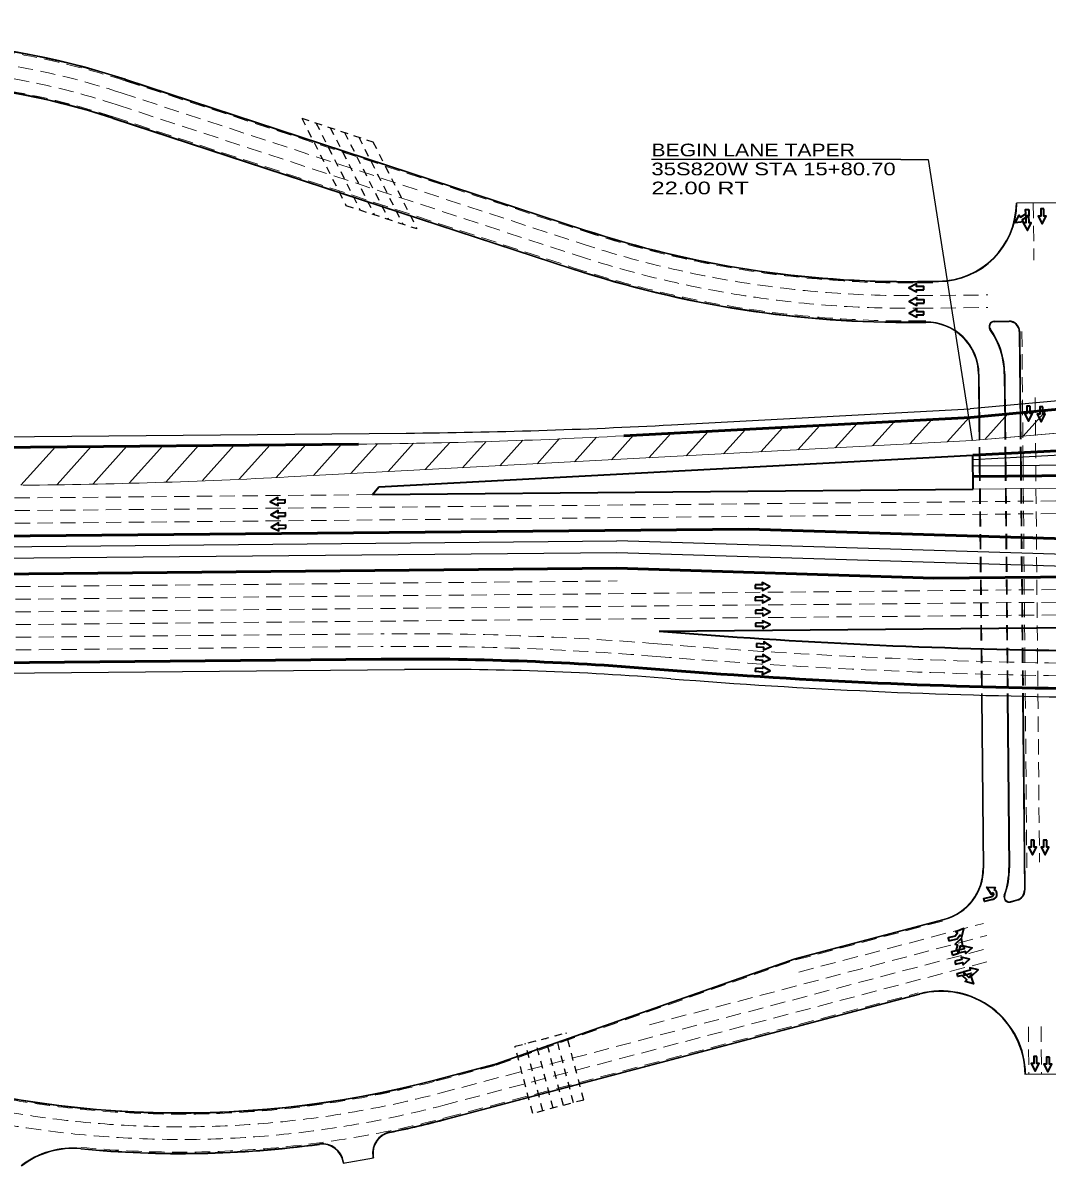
# Model space of a CAD drawing. Extents: x 2326434 to 2368642, y 6985225 to 6995090.
# Drawn here: x 2329823 to 2330793, y 6990688 to 6991772 of the extents above; entities that cross this region are included whole.
import ezdxf

# ---------------------------------------------------------------- set-up
doc = ezdxf.new("R2010")
doc.units = 0
doc.header["$LTSCALE"] = 4.8
doc.linetypes.add('MEDIUM_DASHED', pattern=[4.5, 3, -1.5])
doc.linetypes.add('SHORT_DASHED', pattern=[2.7, 1.5, -1.2])
for name, color, linetype, lineweight in [('10', 7, 'Continuous', 35), ('26', 7, 'Continuous', 25), ('27', 7, 'Continuous', 25), ('28', 7, 'Continuous', 25), ('33', 7, 'SHORT_DASHED', 25), ('40', 7, 'Continuous', 35), ('5', 7, 'Continuous', 25), ('50', 7, 'MEDIUM_DASHED', 13)]:
    doc.layers.add(name, color=color, linetype=linetype, lineweight=lineweight)

msp = doc.modelspace()

# ---------------------------------------------------------------- linework, layer by layer
at = {"layer": '10'}
for p, q in [((2330160.246, 6991332.035), (2330723.1, 6991362.027)), ((2330723.399, 6991330.029), (2330723.1, 6991362.028)), ((2330154.405, 6991324.713), (2330160.246, 6991332.035)), ((2330154.405, 6991324.713), (2330723.399, 6991330.029)), ((2330426.072, 6991195.246), (2330819.65, 6991198.923))]:
    msp.add_line(p, q, dxfattribs=at)
for centre, radius, start, end in [((2331921.237, 6992748.984), 1265.239, 273.05017, 273.05017), ((2330888.37, 6996870.024), 5693.578, 265.34266, 269.30964)]:
    msp.add_arc(centre, radius, start, end, dxfattribs=at)
at = {"layer": '26'}
for p, q in [((2329663.567, 6991378.13), (2330186.355, 6991383.014)), ((2330723.193, 6991352.028), (2332252.211, 6991366.314)), ((2329664.538, 6991274.135), (2330385.724, 6991280.873)), ((2329665.659, 6991154.14), (2330184.765, 6991158.99))]:
    msp.add_line(p, q, dxfattribs=at)
at = {"layer": '26', "lineweight": 53}
for p, q in [((2329663.66, 6991368.13), (2330141.09, 6991372.591)), ((2330723.287, 6991342.029), (2332252.305, 6991356.314)), ((2329664.445, 6991284.134), (2330510.625, 6991292.04)), ((2330686.071, 6991245.677), (2332092.005, 6991258.812)), ((2329665.566, 6991164.139), (2330162.725, 6991168.784))]:
    msp.add_line(p, q, dxfattribs=at)
at = {"layer": '27', "lineweight": 53}
for p, q in [((2330723.1, 6991362.027), (2332517.509, 6991457.643)), ((2330720.933, 6991397.962), (2331019.869, 6991425.908)), ((2330392.434, 6991380.458), (2330720.933, 6991397.962))]:
    msp.add_line(p, q, dxfattribs=at)
at = {"layer": '27'}
for p, q in [((2330723.061, 6991358.019), (2332517.722, 6991453.649)), ((2331019.444, 6991433.897), (2330720.507, 6991405.951)), ((2330437.699, 6991390.881), (2330720.507, 6991405.951))]:
    msp.add_line(p, q, dxfattribs=at)
for centre, radius, start, end in [((2330132.827, 6997112.342), 5729.578, 270.53529, 273.05017), ((2330211.529, 6988294.326), 2864.789, 85.48726, 90.53529), ((2330888.37, 6996870.024), 5737.578, 265.48726, 269.30964)]:
    msp.add_arc(centre, radius, start, end, dxfattribs=at)
at = {"layer": '27', "lineweight": 53}
for centre, radius, start, end in [((2330189.489, 6988304.12), 2864.789, 85.33564, 90.53529), ((2330888.37, 6996870.024), 5729.578, 265.33564, 269.30964)]:
    msp.add_arc(centre, radius, start, end, dxfattribs=at)
at = {"layer": '28'}
for p, q in [((2329920.311, 6991717.972), (2330355.197, 6991575.35)), ((2329920.467, 6991718.448), (2330355.352, 6991575.825)), ((2329908.313, 6991681.39), (2330343.199, 6991538.767)), ((2329908.469, 6991681.865), (2330343.355, 6991539.242)), ((2330854.998, 6991601.813), (2330764.308, 6991600.966)), ((2330670.791, 6991526.932), (2330690.507, 6991527.116)), ((2330670.795, 6991526.432), (2330690.511, 6991526.616)), ((2330671.15, 6991488.434), (2330678.437, 6991488.502)), ((2330671.155, 6991487.934), (2330678.441, 6991488.002)), ((2330743.365, 6991489.109), (2330757.433, 6991489.24)), ((2330743.369, 6991488.609), (2330757.438, 6991488.74)), ((2330767.026, 6991479.329), (2330767.846, 6991391.636)), ((2330767.526, 6991479.334), (2330768.346, 6991391.658)), ((2330728.402, 6991438.967), (2330728.848, 6991391.288)), ((2330728.902, 6991438.971), (2330729.348, 6991391.293)), ((2330752.901, 6991439.195), (2330753.346, 6991391.517)), ((2330753.401, 6991439.2), (2330753.846, 6991391.522)), ((2330768.138, 6991360.421), (2330768.212, 6991352.449)), ((2330768.637, 6991360.447), (2330768.712, 6991352.454)), ((2330729.155, 6991358.344), (2330729.214, 6991352.085)), ((2330729.655, 6991358.37), (2330729.714, 6991352.089)), ((2330753.644, 6991359.649), (2330753.713, 6991352.314)), ((2330754.144, 6991359.675), (2330754.213, 6991352.318)), ((2330810.865, 6991267.844), (2330385.724, 6991280.873)), ((2329754.855, 6991263.978), (2330385.827, 6991269.873)), ((2330385.827, 6991269.873), (2330810.967, 6991256.844)), ((2330731.258, 6991133.337), (2330732.778, 6990970.753)), ((2330731.758, 6991133.341), (2330733.278, 6990970.758)), ((2330755.757, 6991133.565), (2330757.277, 6990970.982)), ((2330756.257, 6991133.57), (2330757.777, 6990970.987)), ((2330770.256, 6991133.716), (2330771.974, 6990949.936)), ((2330770.757, 6991133.706), (2330772.474, 6990949.941)), ((2330758.703, 6990939.024), (2330764.902, 6990940.662)), ((2330758.831, 6990938.541), (2330765.03, 6990940.179)), ((2330554.86, 6990885.152), (2330695.928, 6990922.434)), ((2330554.987, 6990884.668), (2330696.056, 6990921.95)), ((2330270.934, 6990785.291), (2330554.86, 6990885.152)), ((2330271.081, 6990784.813), (2330554.987, 6990884.668)), ((2330224.442, 6990733.182), (2330672.671, 6990851.642)), ((2330224.569, 6990732.699), (2330672.799, 6990851.158)), ((2330214.604, 6990770.404), (2330270.934, 6990785.291)), ((2330214.732, 6990769.921), (2330271.081, 6990784.813)), ((2330126.563, 6990692.016), (2330126.715, 6990691.036)), ((2330126.715, 6990691.036), (2330155.332, 6990696.033)), ((2330127.057, 6990692.092), (2330127.209, 6990691.113)), ((2330154.619, 6990697.37), (2330154.838, 6990695.956)), ((2330155.113, 6990697.447), (2330155.332, 6990696.033))]:
    msp.add_line(p, q, dxfattribs=at)
at = {"layer": '28', "linetype": 'MEDIUM_DASHED'}
for p, q in [((2330728.848, 6991391.288), (2330729.155, 6991358.344)), ((2330729.348, 6991391.293), (2330729.655, 6991358.37)), ((2330753.346, 6991391.517), (2330753.644, 6991359.649)), ((2330753.846, 6991391.522), (2330754.144, 6991359.675)), ((2330767.846, 6991391.636), (2330768.138, 6991360.421)), ((2330768.346, 6991391.658), (2330768.637, 6991360.447)), ((2330729.214, 6991352.085), (2330731.258, 6991133.337)), ((2330729.714, 6991352.089), (2330731.758, 6991133.341)), ((2330753.713, 6991352.314), (2330755.757, 6991133.565)), ((2330754.213, 6991352.318), (2330756.257, 6991133.57)), ((2330768.212, 6991352.449), (2330770.256, 6991133.716)), ((2330768.712, 6991352.454), (2330770.757, 6991133.706))]:
    msp.add_line(p, q, dxfattribs=at)
at = {"layer": '28', "lineweight": 53}
for p, q in [((2330810.724, 6991282.843), (2330510.625, 6991292.04)), ((2329664.781, 6991248.136), (2330385.967, 6991254.874)), ((2330385.967, 6991254.874), (2330686.071, 6991245.677))]:
    msp.add_line(p, q, dxfattribs=at)
at = {"layer": '28'}
msp.add_lwpolyline([(2330773.606, 6990775.304), (2330805.132, 6990775.611), (2330806.565, 6990715.622)], dxfattribs=at)
for centre, radius, start, end in [((2329689.814, 6991015.138), 740.165, 71.84292, 104.46691), ((2329689.814, 6991015.138), 739.665, 71.84292, 104.46691), ((2329689.814, 6991015.138), 701.665, 71.84292, 104.46691), ((2329689.814, 6991015.138), 701.165, 71.84292, 104.46691), ((2330689.81, 6991601.613), 74.5, 270.53549, 359.50218), ((2330689.81, 6991601.613), 75, 270.53549, 359.50907), ((2330661.606, 6992509.657), 983.268, 251.84292, 270.53549), ((2330661.606, 6992509.657), 982.768, 251.84292, 270.53549), ((2330661.606, 6992509.657), 1021.768, 251.84292, 270.53549), ((2330661.606, 6992509.657), 1021.268, 251.84292, 270.53549), ((2330678.904, 6991438.504), 50, 0.53547, 90.53549), ((2330678.904, 6991438.504), 49.5, 0.53547, 90.53549), ((2330743.411, 6991484.109), 5, 90.53549, 215.25924), ((2330743.411, 6991484.109), 4.5, 90.53549, 215.25924), ((2330678.904, 6991438.504), 74, 0.53547, 35.25924), ((2330678.904, 6991438.504), 74.5, 0.53547, 35.25924), ((2330757.527, 6991479.24), 10, 0.53547, 90.53549), ((2330757.527, 6991479.24), 9.5, 0.53547, 90.53549), ((2330683.28, 6990970.291), 49.5, 284.80383, 0.53547), ((2330683.28, 6990970.291), 50, 284.80383, 0.53547), ((2330683.28, 6990970.291), 74, 340.08008, 0.53546), ((2330683.28, 6990970.291), 74.5, 340.08008, 0.53546), ((2330762.475, 6990949.847), 9.5, 284.80383, 0.53547), ((2330762.475, 6990949.847), 10, 284.80383, 0.53547), ((2330757.553, 6990943.375), 5, 160.08008, 284.80383), ((2330757.553, 6990943.375), 4.5, 160.08008, 284.80383), ((2330693.112, 6990774.297), 80, 0.53547, 104.80383), ((2330693.112, 6990774.297), 79.5, 0.53547, 104.80383), ((2329972.578, 6991686.191), 947.228, 249.88799, 284.80383), ((2329972.578, 6991686.191), 947.728, 249.88799, 284.80383), ((2329972.578, 6991686.191), 985.728, 281.59821, 284.80383), ((2329972.578, 6991686.191), 986.228, 281.59821, 284.80383), ((2330174.877, 6990700.508), 20.5, 101.59821, 188.80445), ((2330174.877, 6990700.508), 20, 101.59821, 188.80445), ((2329870.528, 6990625.36), 80, 84.50515, 127.7674), ((2329870.528, 6990625.36), 79.5, 84.50515, 127.7674), ((2329972.578, 6991686.191), 986.228, 264.50515, 277.66555), ((2329972.578, 6991686.191), 985.728, 264.50515, 277.66555), ((2330106.799, 6990688.954), 20.5, 8.80445, 97.66555), ((2330106.799, 6990688.954), 20, 8.80445, 97.66555)]:
    msp.add_arc(centre, radius, start, end, dxfattribs=at)
at = {"layer": '33'}
for p, q in [((2330087.287, 6991681.647), (2330154.774, 6991659.15)), ((2330100.785, 6991677.148), (2330142.717, 6991594.518)), ((2330114.282, 6991672.648), (2330156.17, 6991590.106)), ((2330127.779, 6991668.149), (2330169.623, 6991585.694)), ((2330141.277, 6991663.649), (2330183.076, 6991581.282)), ((2330154.774, 6991659.15), (2330196.528, 6991576.871)), ((2330335.166, 6990745.771), (2330318.424, 6990809.425)), ((2330344.837, 6990748.314), (2330328.095, 6990811.969)), ((2330354.508, 6990750.858), (2330337.766, 6990814.513)), ((2330315.823, 6990740.684), (2330299.081, 6990804.338)), ((2330325.494, 6990743.227), (2330308.752, 6990806.882)), ((2330354.508, 6990750.858), (2330306.152, 6990738.14))]:
    msp.add_line(p, q, dxfattribs=at)
for points in [[(2330087.287, 6991681.647), (2330129.264, 6991598.93), (2330196.528, 6991576.871)], [(2330306.152, 6990738.14), (2330289.41, 6990801.794), (2330337.766, 6990814.513)]]:
    msp.add_lwpolyline(points, dxfattribs=at)
at = {"layer": '40'}
for points in [[(2330776.129, 6991595.153), (2330776.157, 6991589.169), (2330769.801, 6991585.306), (2330771.188, 6991583.302), (2330763.117, 6991582.313), (2330766.889, 6991589.517), (2330768.094, 6991587.774), (2330773.181, 6991590.923), (2330773.101, 6991595.102)], [(2330776.157, 6991589.169), (2330773.157, 6991589.099), (2330773.315, 6991582.295), (2330770.879, 6991582.238), (2330774.824, 6991575.128), (2330778.434, 6991582.414), (2330776.315, 6991582.364)], [(2330790.375, 6991595.548), (2330787.374, 6991595.548), (2330787.374, 6991588.742), (2330784.937, 6991588.742), (2330788.716, 6991581.542), (2330792.494, 6991588.742), (2330790.375, 6991588.742)], [(2330676.611, 6991518.99), (2330676.609, 6991521.991), (2330669.802, 6991521.986), (2330669.801, 6991524.423), (2330662.603, 6991520.64), (2330669.806, 6991516.866), (2330669.804, 6991518.985)], [(2330676.839, 6991506.284), (2330676.837, 6991509.285), (2330670.03, 6991509.281), (2330670.029, 6991511.718), (2330662.831, 6991507.934), (2330670.034, 6991504.16), (2330670.032, 6991506.28)], [(2330676.759, 6991495.035), (2330676.757, 6991498.036), (2330669.95, 6991498.031), (2330669.948, 6991500.468), (2330662.751, 6991496.685), (2330669.953, 6991492.911), (2330669.952, 6991495.03)], [(2330777.351, 6991408.498), (2330774.351, 6991408.498), (2330774.351, 6991401.691), (2330771.913, 6991401.691), (2330775.692, 6991394.491), (2330779.471, 6991401.691), (2330777.351, 6991401.691)], [(2330789.491, 6991407.838), (2330786.49, 6991407.838), (2330786.49, 6991401.031), (2330784.053, 6991401.031), (2330787.832, 6991393.831), (2330791.61, 6991401.031), (2330789.491, 6991401.031)], [(2330071.621, 6991316.81), (2330071.514, 6991319.809), (2330064.712, 6991319.567), (2330064.625, 6991322.003), (2330057.564, 6991317.971), (2330064.894, 6991314.45), (2330064.818, 6991316.568)], [(2330071.993, 6991304.43), (2330071.887, 6991307.429), (2330065.084, 6991307.188), (2330064.998, 6991309.623), (2330057.936, 6991305.591), (2330065.266, 6991302.07), (2330065.191, 6991304.189)], [(2330072.29, 6991292.847), (2330072.183, 6991295.846), (2330065.381, 6991295.605), (2330065.294, 6991298.04), (2330058.233, 6991294.008), (2330065.562, 6991290.488), (2330065.487, 6991292.606)], [(2330516.877, 6991239.098), (2330516.93, 6991236.098), (2330523.735, 6991236.216), (2330523.778, 6991233.779), (2330530.911, 6991237.683), (2330523.646, 6991241.336), (2330523.683, 6991239.217)], [(2330516.877, 6991239.098), (2330516.93, 6991236.098), (2330523.735, 6991236.216), (2330523.778, 6991233.779), (2330530.911, 6991237.683), (2330523.646, 6991241.336), (2330523.683, 6991239.217)], [(2330516.964, 6991227.512), (2330517.017, 6991224.511), (2330523.822, 6991224.63), (2330523.865, 6991222.193), (2330530.998, 6991226.097), (2330523.733, 6991229.749), (2330523.77, 6991227.63)], [(2330516.964, 6991227.512), (2330517.017, 6991224.511), (2330523.822, 6991224.63), (2330523.865, 6991222.193), (2330530.998, 6991226.097), (2330523.733, 6991229.749), (2330523.77, 6991227.63)], [(2330517.113, 6991215.127), (2330517.165, 6991212.127), (2330523.971, 6991212.246), (2330524.013, 6991209.809), (2330531.147, 6991213.713), (2330523.882, 6991217.365), (2330523.919, 6991215.246)], [(2330517.113, 6991215.127), (2330517.165, 6991212.127), (2330523.971, 6991212.246), (2330524.013, 6991209.809), (2330531.147, 6991213.713), (2330523.882, 6991217.365), (2330523.919, 6991215.246)], [(2330517.214, 6991203.014), (2330517.267, 6991200.014), (2330524.072, 6991200.132), (2330524.115, 6991197.695), (2330531.248, 6991201.599), (2330523.983, 6991205.252), (2330524.02, 6991203.133)], [(2330517.214, 6991203.014), (2330517.267, 6991200.014), (2330524.072, 6991200.132), (2330524.115, 6991197.695), (2330531.248, 6991201.599), (2330523.983, 6991205.252), (2330524.02, 6991203.133)], [(2330518.251, 6991183.466), (2330518.061, 6991180.471), (2330524.854, 6991180.039), (2330524.699, 6991177.607), (2330532.125, 6991180.921), (2330525.179, 6991185.149), (2330525.044, 6991183.034)], [(2330517.373, 6991171.384), (2330517.183, 6991168.389), (2330523.976, 6991167.957), (2330523.821, 6991165.525), (2330531.247, 6991168.839), (2330524.301, 6991173.067), (2330524.166, 6991170.952)], [(2330517.185, 6991160.235), (2330516.994, 6991157.241), (2330523.787, 6991156.809), (2330523.632, 6991154.376), (2330531.058, 6991157.69), (2330524.112, 6991161.919), (2330523.978, 6991159.803)], [(2330781.299, 6990997.228), (2330778.298, 6990997.228), (2330778.298, 6990990.422), (2330775.861, 6990990.422), (2330779.639, 6990983.221), (2330783.418, 6990990.422), (2330781.299, 6990990.422)], [(2330793.116, 6990997.343), (2330790.115, 6990997.343), (2330790.115, 6990990.537), (2330787.678, 6990990.537), (2330791.457, 6990983.337), (2330795.235, 6990990.537), (2330793.116, 6990990.537)], [(2330700.484, 6990901.769), (2330708.2, 6990903.661), (2330710.894, 6990907.121), (2330712.756, 6990905.548), (2330714.516, 6990913.487), (2330706.983, 6990910.425), (2330708.602, 6990909.057), (2330706.477, 6990906.328), (2330699.77, 6990904.683)], [(2330703.669, 6990888.281), (2330709.42, 6990889.934), (2330711.346, 6990897.117), (2330713.659, 6990896.349), (2330712.344, 6990904.373), (2330706.487, 6990898.732), (2330708.498, 6990898.064), (2330706.902, 6990892.298), (2330702.869, 6990891.202)], [(2330709.42, 6990889.934), (2330708.646, 6990892.833), (2330715.222, 6990894.589), (2330714.593, 6990896.944), (2330722.525, 6990895.151), (2330716.544, 6990889.642), (2330715.997, 6990891.69)], [(2330705.93, 6990882.542), (2330706.667, 6990879.634), (2330713.265, 6990881.304), (2330713.864, 6990878.942), (2330719.916, 6990884.372), (2330712.008, 6990886.268), (2330712.529, 6990884.213)], [(2330708.27, 6990870.871), (2330714.087, 6990872.276), (2330719.31, 6990866.982), (2330720.941, 6990868.793), (2330723.762, 6990861.166), (2330715.884, 6990863.177), (2330717.302, 6990864.752), (2330713.066, 6990868.976), (2330709.018, 6990867.936)], [(2330714.087, 6990872.276), (2330714.846, 6990869.373), (2330721.431, 6990871.095), (2330722.048, 6990868.737), (2330728.058, 6990874.214), (2330720.136, 6990876.049), (2330720.672, 6990873.998)], [(2330783.722, 6990792.226), (2330780.721, 6990792.226), (2330780.721, 6990785.419), (2330778.284, 6990785.419), (2330782.062, 6990778.219), (2330785.841, 6990785.419), (2330783.722, 6990785.419)], [(2330795.861, 6990791.566), (2330792.861, 6990791.566), (2330792.861, 6990784.759), (2330790.423, 6990784.759), (2330794.202, 6990777.559), (2330797.981, 6990784.759), (2330795.861, 6990784.759)]]:
    msp.add_lwpolyline(points, close=True, dxfattribs=at)
for points in [[(2330741.781, 6990947.659), (2330740.785, 6990945.798), (2330736.219, 6990952.527), (2330744.351, 6990952.462), (2330743.201, 6990950.313)], [(2330741.836, 6990940.934), (2330734.107, 6990939.096), (2330733.413, 6990942.016), (2330741.351, 6990943.903), (2330741.302, 6990943.894)]]:
    msp.add_lwpolyline(points, dxfattribs=at)
for radius, end in [(4.997, 63.22063), (1.989, 65.29445)]:
    msp.add_arc((2330740.95, 6990945.852), radius, 280.21581, end, dxfattribs=at)
at = {"layer": '5'}
msp.add_line((2330654.791, 6991642.434), (2330418.636, 6991642.434), dxfattribs=at)
msp.add_lwpolyline([(2330654.791, 6991642.434), (2330680.763, 6991642.434), (2330722.355, 6991376.007)], dxfattribs=at)
at = {"layer": '50'}
for p, q in [((2329919.999, 6991717.022), (2330354.885, 6991574.4)), ((2329916.26, 6991705.62), (2330351.145, 6991562.997)), ((2329912.52, 6991694.217), (2330347.406, 6991551.595)), ((2329908.781, 6991682.815), (2330343.667, 6991540.193)), ((2330780.388, 6991601.116), (2330780.893, 6991547.08)), ((2330670.805, 6991525.432), (2330692.09, 6991525.631)), ((2330670.917, 6991513.433), (2330737.201, 6991514.052)), ((2330671.029, 6991501.433), (2330737.313, 6991502.053)), ((2330671.141, 6991489.434), (2330678.427, 6991489.502)), ((2330769.526, 6991479.353), (2330770.637, 6991360.554)), ((2330782.111, 6991416.806), (2330786.229, 6990976.223)), ((2329664.221, 6991308.133), (2332252.529, 6991332.315)), ((2329664.109, 6991320.133), (2330154.405, 6991324.713)), ((2329664.333, 6991296.134), (2332252.641, 6991320.316)), ((2329664.893, 6991236.136), (2330386.079, 6991242.874)), ((2329665.118, 6991212.137), (2332253.426, 6991236.319)), ((2329665.23, 6991200.138), (2332253.538, 6991224.32)), ((2329665.342, 6991188.138), (2330162.501, 6991192.783)), ((2329665.454, 6991176.139), (2330162.613, 6991180.784)), ((2330555.227, 6990883.698), (2330696.311, 6990920.984)), ((2330558.309, 6990872.1), (2330733.337, 6990918.357)), ((2330416.86, 6990822.305), (2330736.403, 6990906.755)), ((2330218.054, 6990757.352), (2330739.469, 6990895.154)), ((2330221.12, 6990745.751), (2330742.536, 6990883.552)), ((2330271.375, 6990783.856), (2330555.342, 6990883.733)), ((2330224.186, 6990734.149), (2330671.418, 6990852.345)), ((2330775.685, 6990820.376), (2330776.106, 6990775.328)), ((2330787.684, 6990820.489), (2330788.105, 6990775.445)), ((2330214.988, 6990768.954), (2330271.375, 6990783.856))]:
    msp.add_line(p, q, dxfattribs=at)
at = {"layer": '50', "linetype": 'Continuous'}
for p, q in [((2330770.799, 6991380.203), (2330792.799, 6991404.681)), ((2330628.053, 6991370.982), (2330648.851, 6991394.121)), ((2330663.358, 6991372.863), (2330684.156, 6991396.003)), ((2330698.663, 6991374.744), (2330719.462, 6991397.884)), ((2331022.739, 6991402.027), (2330722.355, 6991376.007)), ((2330734.346, 6991377.046), (2330756.102, 6991401.25)), ((2330416.221, 6991359.694), (2330437.02, 6991382.834)), ((2330451.527, 6991361.575), (2330472.325, 6991384.715)), ((2330486.832, 6991363.457), (2330507.63, 6991386.596)), ((2330522.137, 6991365.338), (2330542.935, 6991388.477)), ((2330557.442, 6991367.219), (2330578.241, 6991390.359)), ((2330592.748, 6991369.101), (2330613.546, 6991392.24)), ((2330141.09, 6991372.591), (2329663.66, 6991368.13)), ((2329923.876, 6991335.501), (2329955.656, 6991370.859)), ((2329958.549, 6991336.679), (2329989.555, 6991371.175)), ((2329993.332, 6991337.979), (2330023.454, 6991371.492)), ((2330028.115, 6991339.28), (2330057.353, 6991371.809)), ((2330063.204, 6991340.92), (2330091.252, 6991372.125)), ((2330074.514, 6991341.486), (2330722.355, 6991376.007)), ((2330098.474, 6991342.763), (2330125.151, 6991372.442)), ((2330133.779, 6991344.644), (2330159.103, 6991372.818)), ((2330169.085, 6991346.525), (2330193.272, 6991373.435)), ((2330204.39, 6991348.407), (2330227.666, 6991374.303)), ((2330239.695, 6991350.288), (2330262.06, 6991375.17)), ((2330275, 6991352.169), (2330296.645, 6991376.251)), ((2330310.306, 6991354.05), (2330331.641, 6991377.788)), ((2330345.611, 6991355.932), (2330366.637, 6991379.325)), ((2330380.916, 6991357.813), (2330401.714, 6991380.952)), ((2329821.326, 6991333.602), (2329853.959, 6991369.908)), ((2329855.498, 6991334.223), (2329887.858, 6991370.225)), ((2329889.687, 6991334.862), (2329921.757, 6991370.542)), ((2330723.399, 6991330.029), (2331404.275, 6991336.391))]:
    msp.add_line(p, q, dxfattribs=at)
for points in [[(2331988.987, 6991477.549), (2331019.869, 6991425.908), (2330720.933, 6991397.962), (2330392.434, 6991380.458)], [(2330074.514, 6991341.486), (2330722.355, 6991376.007), (2331022.739, 6991402.027), (2331911.828, 6991449.403)]]:
    msp.add_lwpolyline(points, dxfattribs=at)
at = {"layer": '50'}
for points in [[(2330770.637, 6991360.554), (2330770.712, 6991352.472), (2330774.304, 6990968.169)], [(2329665.005, 6991224.137), (2332090.455, 6991246.797), (2332253.314, 6991248.319)]]:
    msp.add_lwpolyline(points, dxfattribs=at)
for centre, radius, start, end in [((2329689.814, 6991015.138), 738.665, 71.84292, 104.46691), ((2329689.814, 6991015.138), 726.665, 71.84292, 104.46691), ((2329689.814, 6991015.138), 714.665, 71.84292, 104.46691), ((2329689.814, 6991015.138), 702.665, 71.84292, 104.46691), ((2330661.606, 6992509.657), 984.268, 251.84292, 270.53549), ((2330661.606, 6992509.657), 996.268, 251.84292, 270.53549), ((2330661.606, 6992509.657), 1008.268, 251.84292, 270.53549), ((2330661.606, 6992509.657), 1020.268, 251.84292, 270.53549), ((2330189.489, 6988304.12), 2888.789, 85.33564, 90.53529), ((2330189.489, 6988304.12), 2876.789, 85.33564, 90.53529), ((2330888.37, 6996870.024), 5705.578, 265.33564, 269.30964), ((2330888.37, 6996870.024), 5717.578, 265.33564, 269.30964), ((2329972.578, 6991686.191), 948.728, 249.88799, 284.80383), ((2329972.578, 6991686.191), 960.728, 249.88799, 284.80383), ((2329972.578, 6991686.191), 972.728, 249.88799, 284.80383), ((2329972.578, 6991686.191), 984.728, 264.50515, 284.80383)]:
    msp.add_arc(centre, radius, start, end, dxfattribs=at)
at = {"layer": '50', "linetype": 'Continuous'}
for centre in [(2330087.562, 6997101.919), (2329769.642, 6997062.947), (2329769.642, 6997062.947)]:
    msp.add_arc(centre, 5729.578, 270.53529, 273.05017, dxfattribs=at)

# ---------------------------------------------------------------- texts
at = {"layer": '5'}
for s, width, p in [('BEGIN LANE TAPER', 1.25, (2330418.636, 6991645.434)), ('35S820W STA 15+80.70', 1.3, (2330418.636, 6991627.434)), ('22.00 RT', 1.4, (2330418.636, 6991609.434))]:
    msp.add_text(s, height=12, dxfattribs=dict(at, width=width)).set_placement(p)

doc.saveas('drawing.dxf')
